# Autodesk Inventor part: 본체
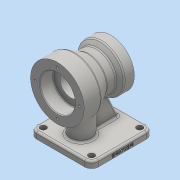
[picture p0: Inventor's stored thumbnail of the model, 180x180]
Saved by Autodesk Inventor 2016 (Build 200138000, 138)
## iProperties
Created: 2019-01
Part Number: 본체
Material: Generic
Document SubType Name: Modeling
Designer: 2-PC10
Density: 1 g/cm^3
Appearance: Default
Mass: 332.895 g
Surface Area: 600.964 cm^2
Volume: 332.895 cm^3
Author: 2-PC10
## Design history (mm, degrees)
sketch "스케치1"
  geometry: L1 (-46, -46)-(46, -46); L2 (46, -46)-(46, 46); L3 (46, 46)-(-46, 46); L4 (-46, 46)-(-46, -46); L5 (-46, -46)-(46, 46); L6 (46, -46)-(-46, 46); 1 further point
  constraints: 12 end point, 2 midpoint, 2 parallel, 1 horizontal, 1 perpendicular
  dimensions: "d0" = 92 distance of L3.end L2.end; "d1" = 92 distance of L2.end L1.end
extrude "돌출1" new body sketch "스케치1" distance "d2" = 10; taper "d3" = 0 deg
sketch "스케치2"
  geometry: L1 (-51, 80)-(-51, 120); L2 (-51, 120)-(-26, 120); L3 (-26, 120)-(-5.215, 108); L4 (-5.215, 108)-(8.126, 108); L5 (14, 115)-(29, 115); L6 (29, 115)-(29, 80); L7 (29, 80)-(-51, 80); L8 (-46, 0)-(46, 0) reference; L9 (-46, 0)-(-46, 10) reference; L10 (14, 115)-(8.126, 108); 1 further point
  constraints: 16 end point, 3 perpendicular, 2 parallel, 1 vertical
  dimensions: "d4" = 25 distance of L1.end L2.end; "d7" = 80 diameter of L2 L7; "d8" = 56 diameter of L4 L7; "d9" = 70 diameter of L5 L7; "d10" = 80 distance between parallel lines of L8 L7; "d11" = 5 distance between parallel lines of L9 L1; "d12" = 30 deg angle of L4 L3; "d13" = 50 deg angle of L4 L10; "d14" = 15 distance of L5.start L5.end; "d15" = 80 distance between parallel lines of L6 L1
revolve "회전1" sketch "스케치2" stored, may be unused: angle "d16" = 90 deg
sketch "스케치3"
  geometry: L1 (-46, -46)-(46, -46) reference; C1 r 16 at (0, -16); 1 further point
  constraints: 1 centre point, 1 vertical alignment
  dimensions: "d17" = 16 radius of C1; "d18" = 30 distance from line of C1.centre L1
extrude "돌출2" join sketch "스케치3" stored distance "d19" = 10; taper "d20" = 0 deg
sketch "스케치4"
  geometry: L1 (21.486, 41.126)-(36, 10); L2 (46, 0)-(46, 10) reference; L3 (-46, 10)-(46, 10) reference; 1 further point
  constraints: 2 end point, 1 point on line
  dimensions: "d21" = 25 deg angle of L2 L1; "d22" = 10 distance from line of L2 L1.end
feature "리브1" sketch "스케치4" dims "d23" = 1, "d24" = 10, "d25" = 0, "d26" = 0, "d27" = 1, "d28" = 1
sketch "스케치5"
  geometry: L1 (-51, 106)-(-31, 106); L2 (-31, 106)-(-31, 96); L3 (-31, 96)-(12, 96); L4 (12, 96)-(12, 100); L5 (12, 100)-(29, 100); L6 (29, 100)-(29, 80); L7 (29, 80)-(-51, 80); L8 (-51, 80)-(-51, 106); L9 (-51, 40)-(-51, 120) reference; L10 (29, 45)-(29, 115) reference; L11 (46, 0)-(-46, 0) reference; 1 further point
  constraints: 16 end point, 7 perpendicular, 2 collinear, 1 horizontal
  dimensions: "d29" = 52 diameter of L1 L7; "d30" = 32 diameter of L3 L7; "d31" = 40 diameter of L5 L7; "d32" = 80 distance between parallel lines of L11 L7; "d33" = 20 distance of L1.start L1.end; "d34" = 17 distance of L4.end L5.end
revolve "회전2" sketch "스케치5" stored, may be unused: angle "d35" = 90 deg
sketch "스케치6" dims "d36" = 66
  geometry: C1 r 40 at (0, 0) reference; 3 further points
  constraints: 2 vertical alignment, 3 other
hole "구멍1" sketch "스케치6" at (0, 33) diameter "d37" = 3.242; stored, may be unused: countersink angle "d41" = 90 deg, drill point angle "d43" = 118 deg; dims "d38" = 9, "d39" = 4, "d40" = 2, "d42" = 11
sketch "스케치7" dims "d47" = 55
  geometry: C1 r 35 at (0, 0) reference; 3 further points
  constraints: 2 vertical alignment, 3 other
hole "구멍2" sketch "스케치7" at (0, -27.5) diameter "d48" = 3.242; stored, may be unused: countersink angle "d52" = 90 deg, drill point angle "d54" = 118 deg; dims "d49" = 9, "d50" = 4, "d51" = 2, "d53" = 11
fillet "모깎기1" dims "d58" = 1
fillet "모깎기2" dims "d59" = 0.6
fillet "모깎기3" dims "d60" = 3
fillet "모깎기4" dims "d61" = 3
fillet "모깎기5" dims "d62" = 3
fillet "모깎기6" dims "d63" = 3
fillet "모깎기7" dims "d64" = 10
fillet "모깎기8" dims "d65" = 3
hole "구멍3" diameter "d68" = 9; stored, may be unused: countersink angle "d72" = 90 deg, drill point angle "d74" = 0 deg; dims "d66" = 10, "d67" = 10, "d69" = 9, "d70" = 4, "d71" = 2, "d73" = 11
chamfer "모따기1" distance "d81" = 1; stored, may be unused: second distance "d82" = 2, angle "d83" = 45 deg
sketch "스케치8"
  geometry: L1 (-7.5, 18.5)-(-7.5, 53.5); L2 (-7.5, 53.5)-(-0.5, 53.5); L3 (-0.5, 53.5)-(-0.5, 18.5); L4 (-0.5, 18.5)-(-7.5, 18.5); L5 (-4, 18.5)-(-4, 53.5); L6 (-7.5, 36)-(-0.5, 36); L7 (-7, -10)-(0, -10) reference; L8 (0, 0)-(0, 72) reference; 1 further point
  constraints: 4 end point, 4 midpoint, 2 other
  dimensions: "d84" = 46 distance between parallel lines of L6 L7; "d85" = 4 distance between parallel lines of L8 L5; "d86" = 35 distance of L1.start L1.end; "d87" = 7 distance of L1.end L2.end
feature "엠보싱1" sketch "스케치8" dims "d0" = 92, "d1" = 92, "d88" = 0.5, "d89" = 0
node "솔리드1"
pattern_circular "원형 패턴1" dims angle "d45" = 360 deg
pattern_circular "원형 패턴2" dims angle "d56" = 360 deg
pattern_linear "직사각형 패턴1" dims "d77" = 72, "d80" = 72
